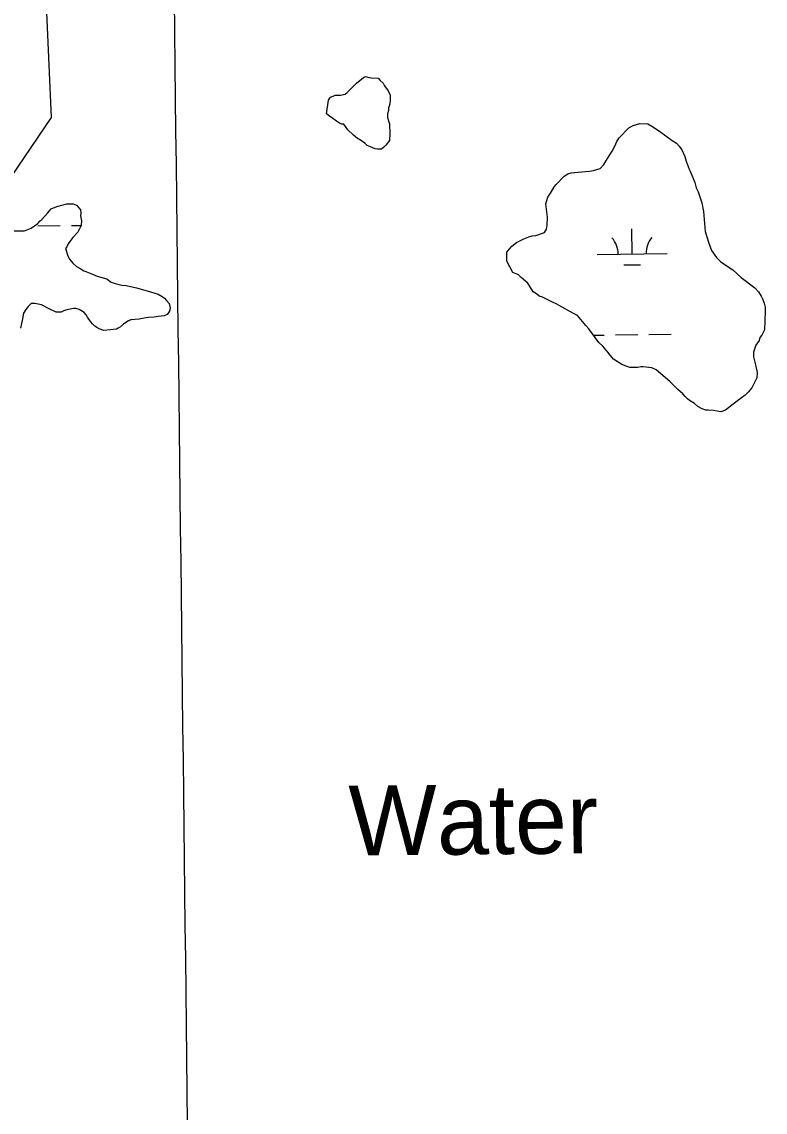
# Model space of a CAD drawing. Extents: x 3702978 to 3741108, y 397120 to 422907.
# Drawn here: x 3709567 to 3710630, y 406884 to 408444 of the extents above; entities that cross this region are included whole.
import ezdxf

# ---------------------------------------------------------------- set-up
doc = ezdxf.new("R2010")
doc.units = 0
for name, color, linetype in [('V-GRID-MAJR', 7, 'Continuous'), ('V-RIVR-IDEN', 7, 'Continuous'), ('V-TOPO-BNDY', 7, 'Continuous'), ('V-TOPO-SHOR', 7, 'Continuous'), ('V-WETL-SWMP', 7, 'Continuous')]:
    doc.layers.add(name, color=color, linetype=linetype)

msp = doc.modelspace()

# ---------------------------------------------------------------- linework, layer by layer
at = {"layer": 'V-GRID-MAJR'}
msp.add_spline([(3709855.178, 402559.365), (3709783.788, 408618.69), (3709712.386, 414679.078), (3709640.983, 420739.47), (3709640.971, 420740.528)], degree=3, dxfattribs=at)
at = {"layer": 'V-TOPO-BNDY'}
for p, q in [((3709609.881, 408306.828), (3709593.302, 408661.849)), ((3709516.117, 408169.465), (3709609.881, 408306.828))]:
    msp.add_line(p, q, dxfattribs=at)
at = {"layer": 'V-TOPO-SHOR'}
msp.add_lwpolyline([(3710007.049, 408308.77), (3710002.9, 408312.103), (3710005.952, 408331.92), (3710008.603, 408336.057), (3710012.666, 408337.493), (3710015.367, 408338.904), (3710022.861, 408339.039), (3710029.649, 408340.524), (3710032.337, 408342.617), (3710041.716, 408351.644), (3710045.73, 408355.805), (3710055.802, 408364.164), (3710058.503, 408365.575), (3710063.978, 408364.311), (3710067.396, 408363.691), (3710076.946, 408363.18), (3710079.732, 408359.823), (3710083.893, 408355.809), (3710085.998, 408352.439), (3710090.902, 408345.031), (3710093.737, 408338.949), (3710093.859, 408332.136), (3710093.276, 408326.674), (3710092.656, 408323.255), (3710091.342, 408320.505), (3710091.403, 408317.099), (3710090.126, 408312.306), (3710090.224, 408306.856), (3710091.672, 408302.111), (3710093.108, 408298.048), (3710093.365, 408283.742), (3710092.855, 408274.192), (3710087.527, 408267.281), (3710084.851, 408264.507), (3710081.494, 408261.721), (3710076.044, 408261.623), (3710072.625, 408262.243), (3710065.763, 408264.846), (3710060.958, 408266.804), (3710057.49, 408270.149), (3710049.899, 408275.465), (3710047.149, 408276.779), (3710041.613, 408281.45), (3710033.291, 408289.478), (3710027.695, 408297.555), (3710024.288, 408297.494), (3710021.539, 408298.808), (3710017.402, 408301.459), (3710011.879, 408305.449)], close=True, dxfattribs=at)
for points in [[(3710379.185, 408230.266), (3710384.623, 408231.045), (3710394.112, 408233.941), (3710399.464, 408239.489), (3710404.755, 408248.444), (3710411.385, 408258.785), (3710415.35, 408265.671), (3710417.953, 408272.532), (3710421.261, 408278.044), (3710435.323, 408291.926), (3710441.393, 408295.442), (3710450.882, 408298.339), (3710462.476, 408297.865), (3710467.987, 408294.557), (3710479.022, 408287.259), (3710496.979, 408273.951), (3710503.184, 408269.974), (3710507.345, 408265.96), (3710510.849, 408260.571), (3710515.108, 408251.106), (3710517.274, 408244.33), (3710521.57, 408232.822), (3710522.981, 408230.122), (3710529.406, 408213.882), (3710531.584, 408206.424), (3710534.42, 408200.342), (3710539.47, 408184.758), (3710541.734, 408172.532), (3710544.291, 408143.956), (3710549.366, 408127.01), (3710553.637, 408116.864), (3710560.633, 408106.768), (3710566.193, 408100.734), (3710575.853, 408094.093), (3710584.126, 408088.79), (3710595.904, 408078.097), (3710615.248, 408063.452), (3710620.808, 408057.418), (3710624.325, 408051.348), (3710626.442, 408047.297), (3710628.596, 408041.203), (3710630.056, 408035.777), (3710630.166, 408029.646), (3710629.281, 408003.052), (3710625.328, 407995.484), (3710622.664, 407992.029), (3710621.375, 407987.917), (3710616.728, 407981.019), (3710613.493, 407971.42), (3710613.615, 407964.607), (3710616.585, 407951.031), (3710618.788, 407942.211), (3710618.241, 407934.705), (3710613.644, 407925.082), (3710611.004, 407920.264), (3710605.664, 407914.035), (3710601.65, 407909.874), (3710596.273, 407905.688), (3710584.169, 407896.612), (3710573.416, 407888.241), (3710566.64, 407886.075), (3710556.384, 407887.935), (3710548.878, 407888.482), (3710545.472, 407888.421), (3710539.985, 407890.367), (3710533.793, 407893.663), (3710528.95, 407897.665), (3710522.052, 407902.311), (3710519.29, 407904.306), (3710515.823, 407907.651), (3710512.343, 407911.678), (3710505.42, 407917.687), (3710493.631, 407929.06), (3710474.25, 407945.75), (3710468.057, 407949.046), (3710455.77, 407950.188), (3710452.364, 407950.127), (3710448.288, 407949.372), (3710436.707, 407949.164), (3710431.22, 407951.11), (3710425.04, 407953.725), (3710413.324, 407961.011), (3710408.445, 407967.057), (3710404.965, 407971.083), (3710397.993, 407979.818), (3710392.445, 407985.17), (3710377.784, 408004.67), (3710373.611, 408009.365), (3710361.773, 408023.464), (3710356.261, 408026.772), (3710335.615, 408037.987), (3710332.172, 408039.969), (3710325.992, 408042.584), (3710311.551, 408049.821), (3710306.758, 408051.098), (3710303.29, 408054.443), (3710298.46, 408057.764), (3710290.746, 408069.892), (3710281.062, 408077.896), (3710277.582, 408081.923), (3710269.346, 408085.182)], [(3710269.346, 408085.182), (3710260.877, 408101.386), (3710260.644, 408114.33), (3710267.992, 408122.639), (3710274.706, 408128.212), (3710277.407, 408129.623), (3710284.84, 408133.164), (3710292.285, 408136.024), (3710297.029, 408137.472), (3710302.467, 408138.251), (3710314.656, 408142.559), (3710317.296, 408147.377), (3710318.56, 408152.851), (3710319.034, 408164.445), (3710316.647, 408183.484), (3710319.201, 408193.07), (3710323.191, 408198.594), (3710329.151, 408208.242), (3710331.146, 408211.003), (3710342.519, 408222.793), (3710347.908, 408226.297), (3710352.653, 408227.745), (3710367.616, 408229.377), (3710379.185, 408230.266)], [(3709555.446, 408144.601), (3709571.116, 408144.883), (3709580.592, 408148.46), (3709590.007, 408155.444), (3709593.353, 408158.912), (3709596.041, 408161.004), (3709604.057, 408170.008), (3709609.397, 408176.237), (3709617.511, 408179.79)], [(3709617.511, 408179.79), (3709631.757, 408183.453), (3709640.613, 408183.612), (3709645.419, 408181.654), (3709648.898, 408177.628), (3709650.991, 408174.939), (3709651.77, 408169.501), (3709651.15, 408166.083), (3709652.635, 408159.295), (3709652.076, 408152.47), (3709647.478, 408142.846), (3709640.119, 408135.218), (3709636.129, 408129.695), (3709633.465, 408126.239), (3709631.495, 408122.115), (3709629.5, 408119.353), (3709633.09, 408109.195), (3709635.219, 408104.463), (3709640.098, 408098.418), (3709645.634, 408093.747), (3709651.827, 408090.45), (3709655.963, 408087.799), (3709658.713, 408086.485), (3709668.324, 408082.569), (3709675.185, 408079.966), (3709683.409, 408077.388), (3709688.884, 408076.123), (3709695.101, 408071.464), (3709700.588, 408069.518), (3709710.174, 408066.964), (3709716.318, 408066.393), (3709731.367, 408063.256), (3709743.01, 408060.058), (3709746.44, 408058.756), (3709762.195, 408054.269), (3709767.706, 408050.96), (3709771.162, 408048.296), (3709773.948, 408044.939), (3709778.109, 408040.925), (3709779.581, 408034.818), (3709778.304, 408030.025), (3709774.984, 408025.195), (3709770.933, 408023.077), (3709762.089, 408022.237), (3709756.651, 408021.458), (3709748.488, 408020.63), (3709742.369, 408019.839), (3709734.899, 408018.342), (3709723.33, 408017.452), (3709719.948, 408016.029), (3709717.248, 408014.617), (3709712.54, 408011.125), (3709708.513, 408007.646), (3709705.144, 408005.541), (3709702.443, 408004.129), (3709684.755, 408002.449), (3709677.905, 408004.37), (3709674.462, 408006.353), (3709671.701, 408008.348), (3709668.233, 408011.693), (3709665.447, 408015.05), (3709661.249, 408021.108), (3709659.144, 408024.478), (3709656.358, 408027.835), (3709649.46, 408032.482), (3709644.667, 408033.759), (3709641.26, 408033.697), (3709636.504, 408032.931), (3709629.715, 408031.446), (3709626.334, 408030.022), (3709623.633, 408028.611), (3709616.139, 408028.476), (3709606.516, 408033.074), (3709595.505, 408039.009), (3709585.931, 408040.882), (3709580.481, 408040.784), (3709576.467, 408036.623), (3709573.134, 408032.474), (3709569.825, 408026.963), (3709567.965, 408016.707), (3709565.436, 408005.758)]]:
    msp.add_lwpolyline(points, dxfattribs=at)
at = {"layer": 'V-WETL-SWMP'}
for p, q in [((3709590.125, 408151.803), (3709622.122, 408152.201)), ((3709638.121, 408152.399), (3709652.084, 408152.573)), ((3710439.914, 408111.613), (3710439.467, 408147.611)), ((3710389.918, 408110.992), (3710489.91, 408112.235)), ((3710428.106, 408096.035), (3710452.104, 408096.333)), ((3710384.689, 407995.487), (3710399.943, 407995.676)), ((3710415.941, 407995.875), (3710447.939, 407996.272)), ((3710463.938, 407996.471), (3710495.935, 407996.868))]:
    msp.add_line(p, q, dxfattribs=at)
msp.add_lwpolyline([(3710007.049, 408308.77), (3710002.9, 408312.103), (3710005.952, 408331.92), (3710008.603, 408336.057), (3710012.666, 408337.493), (3710015.367, 408338.904), (3710022.861, 408339.039), (3710029.649, 408340.524), (3710032.337, 408342.617), (3710041.716, 408351.644), (3710045.73, 408355.805), (3710055.802, 408364.164), (3710058.503, 408365.575), (3710063.978, 408364.311), (3710067.396, 408363.691), (3710076.946, 408363.18), (3710079.732, 408359.823), (3710083.893, 408355.809), (3710085.998, 408352.439), (3710090.902, 408345.031), (3710093.737, 408338.949), (3710093.859, 408332.136), (3710093.276, 408326.674), (3710092.656, 408323.255), (3710091.342, 408320.505), (3710091.403, 408317.099), (3710090.126, 408312.306), (3710090.224, 408306.856), (3710091.672, 408302.111), (3710093.108, 408298.048), (3710093.365, 408283.742), (3710092.855, 408274.192), (3710087.527, 408267.281), (3710084.851, 408264.507), (3710081.494, 408261.721), (3710076.044, 408261.623), (3710072.625, 408262.243), (3710065.763, 408264.846), (3710060.958, 408266.804), (3710057.49, 408270.149), (3710049.899, 408275.465), (3710047.149, 408276.779), (3710041.613, 408281.45), (3710033.291, 408289.478), (3710027.695, 408297.555), (3710024.288, 408297.494), (3710021.539, 408298.808), (3710017.402, 408301.459), (3710011.879, 408305.449)], close=True, dxfattribs=at)
for points in [[(3710379.185, 408230.266), (3710384.623, 408231.045), (3710394.112, 408233.941), (3710399.464, 408239.489), (3710404.755, 408248.444), (3710411.385, 408258.785), (3710415.35, 408265.671), (3710417.953, 408272.532), (3710421.261, 408278.044), (3710435.323, 408291.926), (3710441.393, 408295.442), (3710450.882, 408298.339), (3710462.476, 408297.865), (3710467.987, 408294.557), (3710479.022, 408287.259), (3710496.979, 408273.951), (3710503.184, 408269.974), (3710507.345, 408265.96), (3710510.849, 408260.571), (3710515.108, 408251.106), (3710517.274, 408244.33), (3710521.57, 408232.822), (3710522.981, 408230.122), (3710529.406, 408213.882), (3710531.584, 408206.424), (3710534.42, 408200.342), (3710539.47, 408184.758), (3710541.734, 408172.532), (3710544.291, 408143.956), (3710549.366, 408127.01), (3710553.637, 408116.864), (3710560.633, 408106.768), (3710566.193, 408100.734), (3710575.853, 408094.093), (3710584.126, 408088.79), (3710595.904, 408078.097), (3710615.248, 408063.452), (3710620.808, 408057.418), (3710624.325, 408051.348), (3710626.442, 408047.297), (3710628.596, 408041.203), (3710630.056, 408035.777), (3710630.166, 408029.646), (3710629.281, 408003.052), (3710625.328, 407995.484), (3710622.664, 407992.029), (3710621.375, 407987.917), (3710616.728, 407981.019), (3710613.493, 407971.42), (3710613.615, 407964.607), (3710616.585, 407951.031), (3710618.788, 407942.211), (3710618.241, 407934.705), (3710613.644, 407925.082), (3710611.004, 407920.264), (3710605.664, 407914.035), (3710601.65, 407909.874), (3710596.273, 407905.688), (3710584.169, 407896.612), (3710573.416, 407888.241), (3710566.64, 407886.075), (3710556.384, 407887.935), (3710548.878, 407888.482), (3710545.472, 407888.421), (3710539.985, 407890.367), (3710533.793, 407893.663), (3710528.95, 407897.665), (3710522.052, 407902.311), (3710519.29, 407904.306), (3710515.823, 407907.651), (3710512.343, 407911.678), (3710505.42, 407917.687), (3710493.631, 407929.06), (3710474.25, 407945.75), (3710468.057, 407949.046), (3710455.77, 407950.188), (3710452.364, 407950.127), (3710448.288, 407949.372), (3710436.707, 407949.164), (3710431.22, 407951.11), (3710425.04, 407953.725), (3710413.324, 407961.011), (3710408.445, 407967.057), (3710404.965, 407971.083), (3710397.993, 407979.818), (3710392.445, 407985.17), (3710377.784, 408004.67), (3710373.611, 408009.365), (3710361.773, 408023.464), (3710356.261, 408026.772), (3710335.615, 408037.987), (3710332.172, 408039.969), (3710325.992, 408042.584), (3710311.551, 408049.821), (3710306.758, 408051.098), (3710303.29, 408054.443), (3710298.46, 408057.764), (3710290.746, 408069.892), (3710281.062, 408077.896), (3710277.582, 408081.923), (3710269.346, 408085.182)], [(3710269.346, 408085.182), (3710260.877, 408101.386), (3710260.644, 408114.33), (3710267.992, 408122.639), (3710274.706, 408128.212), (3710277.407, 408129.623), (3710284.84, 408133.164), (3710292.285, 408136.024), (3710297.029, 408137.472), (3710302.467, 408138.251), (3710314.656, 408142.559), (3710317.296, 408147.377), (3710318.56, 408152.851), (3710319.034, 408164.445), (3710316.647, 408183.484), (3710319.201, 408193.07), (3710323.191, 408198.594), (3710329.151, 408208.242), (3710331.146, 408211.003), (3710342.519, 408222.793), (3710347.908, 408226.297), (3710352.653, 408227.745), (3710367.616, 408229.377), (3710379.185, 408230.266)], [(3709555.446, 408144.601), (3709571.116, 408144.883), (3709580.592, 408148.46), (3709590.007, 408155.444), (3709593.353, 408158.912), (3709596.041, 408161.004), (3709604.057, 408170.008), (3709609.397, 408176.237), (3709617.511, 408179.79)], [(3709617.511, 408179.79), (3709631.757, 408183.453), (3709640.613, 408183.612), (3709645.419, 408181.654), (3709648.898, 408177.628), (3709650.991, 408174.939), (3709651.77, 408169.501), (3709651.15, 408166.083), (3709652.635, 408159.295), (3709652.076, 408152.47), (3709647.478, 408142.846), (3709640.119, 408135.218), (3709636.129, 408129.695), (3709633.465, 408126.239), (3709631.495, 408122.115), (3709629.5, 408119.353), (3709633.09, 408109.195), (3709635.219, 408104.463), (3709640.098, 408098.418), (3709645.634, 408093.747), (3709651.827, 408090.45), (3709655.963, 408087.799), (3709658.713, 408086.485), (3709668.324, 408082.569), (3709675.185, 408079.966), (3709683.409, 408077.388), (3709688.884, 408076.123), (3709695.101, 408071.464), (3709700.588, 408069.518), (3709710.174, 408066.964), (3709716.318, 408066.393), (3709731.367, 408063.256), (3709743.01, 408060.058), (3709746.44, 408058.756), (3709762.195, 408054.269), (3709767.706, 408050.96), (3709771.162, 408048.296), (3709773.948, 408044.939), (3709778.109, 408040.925), (3709779.581, 408034.818), (3709778.304, 408030.025), (3709774.984, 408025.195), (3709770.933, 408023.077), (3709762.089, 408022.237), (3709756.651, 408021.458), (3709748.488, 408020.63), (3709742.369, 408019.839), (3709734.899, 408018.342), (3709723.33, 408017.452), (3709719.948, 408016.029), (3709717.248, 408014.617), (3709712.54, 408011.125), (3709708.513, 408007.646), (3709705.144, 408005.541), (3709702.443, 408004.129), (3709684.755, 408002.449), (3709677.905, 408004.37), (3709674.462, 408006.353), (3709671.701, 408008.348), (3709668.233, 408011.693), (3709665.447, 408015.05), (3709661.249, 408021.108), (3709659.144, 408024.478), (3709656.358, 408027.835), (3709649.46, 408032.482), (3709644.667, 408033.759), (3709641.26, 408033.697), (3709636.504, 408032.931), (3709629.715, 408031.446), (3709626.334, 408030.022), (3709623.633, 408028.611), (3709616.139, 408028.476), (3709606.516, 408033.074), (3709595.505, 408039.009), (3709585.931, 408040.882), (3709580.481, 408040.784), (3709576.467, 408036.623), (3709573.134, 408032.474), (3709569.825, 408026.963), (3709567.965, 408016.707), (3709565.436, 408005.758)]]:
    msp.add_lwpolyline(points, dxfattribs=at)
for centre, start, end in [((3710384.669, 408111.402), 359.939883, 41.483542), ((3710495.147, 408112.774), 139.93988, 181.483539)]:
    msp.add_arc(centre, 35.246, start, end, dxfattribs=at)

# ---------------------------------------------------------------- texts
at = {"layer": 'V-RIVR-IDEN'}
msp.add_text('Water', height=99.9998, rotation=0.572928, dxfattribs=at).set_placement((3710034.976, 407251.01))

doc.saveas('drawing.dxf')
